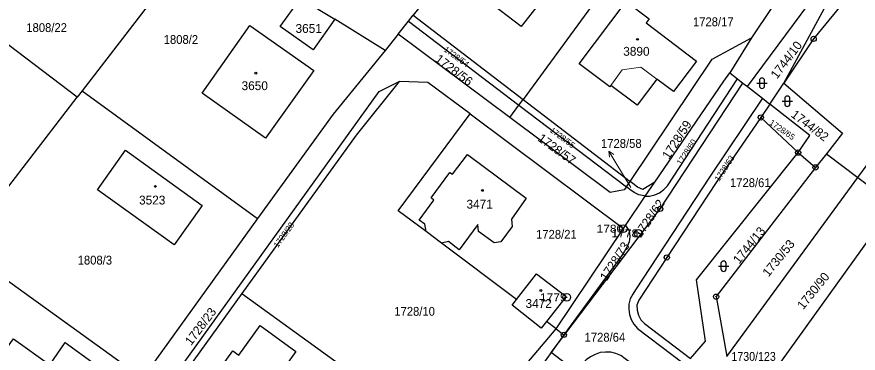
# Model space of a CAD drawing. Extents: x -679733 to -673243, y -1075091 to -1066557.
# Drawn here: x -677143.9 to -676982.3, y -1072239.2 to -1072174.7 of the extents above; entities that cross this region are included whole.
import ezdxf
from ezdxf.enums import TextEntityAlignment as Align

# ---------------------------------------------------------------- set-up
doc = ezdxf.new("R2010")
doc.units = 0
doc.header["$LTSCALE"] = 0.68
for name, color, linetype, lineweight in [('1', 7, 'Continuous', 25), ('3', 7, 'Continuous', 25), ('4', 7, 'Continuous', 13), ('5', 7, 'Continuous', 25), ('7', 7, 'Continuous', 13), ('8', 7, 'Continuous', 25)]:
    doc.layers.add(name, color=color, linetype=linetype, lineweight=lineweight)
doc.layers.add('2', color=7, linetype='Continuous')

msp = doc.modelspace()

# ---------------------------------------------------------------- linework, layer by layer
at = {"layer": '1'}
for p, q in [((-677021.42, -1072156.06), (-677046.63, -1072190.51)), ((-677089.42, -1072171.09), (-677082.85, -1072175.14)), ((-677073.16, -1072181.12), (-677082.85, -1072175.14)), ((-677068.7, -1072175.5), (-677047.45, -1072191.63)), ((-677002.77, -1072178.71), (-677006.93, -1072185.42)), ((-676999.25, -1072191.43), (-676996.56, -1072187.43)), ((-677131.37, -1072188.86), (-677132.33, -1072190.1)), ((-677049.19, -1072194.01), (-677047.45, -1072191.63)), ((-677047.45, -1072191.63), (-677046.63, -1072190.51)), ((-677047.45, -1072191.63), (-677026.81, -1072207.31)), ((-677046.63, -1072190.51), (-677026.1, -1072206.25)), ((-676993.8, -1072200.73), (-676990.45, -1072203.57)), ((-676988.38, -1072200.94), (-676982.32, -1072205.52)), ((-677026.81, -1072207.31), (-677026.1, -1072206.25)), ((-677007.53, -1072239.86), (-676982.32, -1072205.52)), ((-676982.32, -1072205.52), (-676975.41, -1072210.74)), ((-677023.17, -1072209.06), (-677021.37, -1072206.38)), ((-677002.87, -1072248.9), (-676975.41, -1072210.74)), ((-677040.31, -1072234.56), (-677027.35, -1072215.28)), ((-677154.6, -1072218.99), (-677119.75, -1072243.96)), ((-677040.31, -1072234.56), (-677038.82, -1072235.71)), ((-677038.82, -1072235.71), (-677041.29, -1072239.09))]:
    msp.add_line(p, q, dxfattribs=at)
for points in [[(-677003.56, -1072188.05), (-676937.07, -1072098.47), (-676924.77, -1072082.25), (-676901.08, -1072050.53), (-676900.33, -1072051.15)], [(-676926.11, -1072076.11), (-676932.42, -1072084.22), (-676965.77, -1072128.57), (-676982.28, -1072150.91), (-676998.86, -1072172.9), (-677002.77, -1072178.71)], [(-676996.56, -1072187.43), (-676985.94, -1072167.77), (-676927.29, -1072088.05)], [(-676924.4, -1072090.21), (-676960.77, -1072142.26), (-676990.83, -1072178.91), (-676996.56, -1072187.43)], [(-677082.85, -1072175.14), (-677086.97, -1072181.02), (-677093.32, -1072176.54), (-677089.42, -1072171.09), (-677108.59, -1072159.26), (-677131.37, -1072188.86), (-677097.67, -1072213.39)], [(-677056.82, -1072160.52), (-677062.04, -1072167.1), (-677067.77, -1072174.34), (-677046.63, -1072190.51)], [(-677154.6, -1072218.99), (-677132.33, -1072190.1), (-677153.76, -1072173.89), (-677171.45, -1072197.13), (-677175.99, -1072203.1)], [(-677070.68, -1072177.99), (-677068.7, -1072175.5), (-677067.77, -1072174.34)], [(-677026.81, -1072207.31), (-677027.21, -1072207.9), (-677029.93, -1072208.37), (-677049.19, -1072194.01), (-677070.68, -1072177.99), (-677073.16, -1072181.12)], [(-677026.1, -1072206.25), (-677010.31, -1072182.77), (-677002.77, -1072178.71)], [(-677073.16, -1072181.12), (-677083.15, -1072193.33), (-677097.67, -1072213.39), (-677119.75, -1072243.96), (-677138.7, -1072270.17), (-677157.58, -1072296.32)], [(-676982.32, -1072205.52), (-676964.73, -1072181.57), (-676957.44, -1072186.84), (-676936.58, -1072201.92), (-676934.58, -1072203.37)], [(-677023.17, -1072209.06), (-677022.36, -1072209.08), (-677021.37, -1072208.84), (-677020.43, -1072208.43), (-677019.61, -1072207.8), (-677018.91, -1072207.08), (-677005.45, -1072186.58)], [(-677021.37, -1072206.38), (-677008.05, -1072187.02), (-677006.93, -1072185.42)], [(-677006.93, -1072185.42), (-677005.45, -1072186.58), (-677004.4, -1072187.4), (-677003.56, -1072188.05)], [(-677137.29, -1072278.46), (-677138.25, -1072277.77), (-677074.28, -1072189.03), (-677070.45, -1072187.06)], [(-677070.45, -1072187.06), (-677078.7, -1072197.36), (-677100.67, -1072227.78), (-677081.22, -1072241.84), (-677059.66, -1072257.41), (-677040.31, -1072234.56), (-677042.16, -1072233.17)], [(-677056.81, -1072193.31), (-677064.93, -1072187.26), (-677070.45, -1072187.06)], [(-677041.29, -1072239.09), (-677020.3, -1072211.54), (-677004.4, -1072187.4)], [(-677003.56, -1072188.05), (-677000.68, -1072190.31), (-676999.25, -1072191.43)], [(-676996.56, -1072187.43), (-676985.27, -1072196.98), (-676988.38, -1072200.94), (-676990.45, -1072203.57)], [(-677000.68, -1072190.31), (-677010.81, -1072205.46), (-677025.05, -1072227.04), (-677025.58, -1072227.92), (-677026.06, -1072228.81), (-677026.31, -1072229.79), (-677026.34, -1072230.8), (-677026.21, -1072231.82), (-677025.88, -1072232.78), (-677025.36, -1072233.67), (-677024.7, -1072234.47), (-677011.5, -1072244.49)], [(-676999.25, -1072191.43), (-677000.98, -1072193.99), (-676993.8, -1072200.73)], [(-676993.8, -1072200.73), (-676991.56, -1072197.46), (-676999.25, -1072191.43)], [(-677065.31, -1072215.87), (-677070.68, -1072211.91), (-677056.81, -1072193.31)], [(-677056.81, -1072193.31), (-677027.35, -1072215.28), (-677026.98, -1072214.73), (-677023.17, -1072209.06)], [(-677000.98, -1072193.99), (-677009.55, -1072206.46), (-677019.04, -1072220.85), (-677024.42, -1072229.04), (-677024.78, -1072230), (-677024.76, -1072230.97), (-677024.5, -1072231.92), (-677024.01, -1072232.8), (-677023.32, -1072233.51), (-677014.49, -1072240.22)], [(-677065.31, -1072215.87), (-677065.55, -1072214.46), (-677066.63, -1072213.67), (-677063.79, -1072209.83), (-677064.31, -1072209.44), (-677060.7, -1072204.55), (-677060.19, -1072204.89), (-677057.34, -1072201.07), (-677046.04, -1072209.49), (-677048.9, -1072213.51), (-677048.73, -1072214.89), (-677050.93, -1072217.85), (-677052.19, -1072218.04), (-677055.23, -1072215.86), (-677055.36, -1072214.56), (-677058.94, -1072219.38), (-677060.97, -1072217.79), (-677062.31, -1072218.1)], [(-677014.49, -1072240.22), (-677011.6, -1072236.95), (-677013.33, -1072225.14), (-676993.8, -1072200.73)], [(-676990.45, -1072203.57), (-677009.57, -1072228.38), (-677007.53, -1072239.86)], [(-677021.37, -1072206.38), (-677023.64, -1072207.84), (-677024.69, -1072207.39), (-677025.59, -1072206.64), (-677026.1, -1072206.25)], [(-677023.17, -1072209.06), (-677023.38, -1072209.05), (-677024.39, -1072208.85), (-677025.29, -1072208.4), (-677026.13, -1072207.83), (-677026.81, -1072207.31)], [(-677042.16, -1072233.17), (-677043.16, -1072234.45), (-677048.78, -1072230.02), (-677047.9, -1072228.9), (-677062.31, -1072218.1), (-677065.31, -1072215.87)], [(-677026.98, -1072214.73), (-677026.28, -1072215.76), (-677026.13, -1072216.83), (-677026.28, -1072217.83), (-677026.67, -1072218.76), (-677027.15, -1072219.65), (-677027.69, -1072220.49), (-677038.82, -1072235.71)], [(-677047.9, -1072228.9), (-677044.06, -1072224.02), (-677038.38, -1072228.38), (-677042.16, -1072233.17)], [(-677100.67, -1072227.78), (-677124.1, -1072260.21), (-677104.64, -1072274.26)], [(-677104.87, -1072255.34), (-677104.07, -1072254.32), (-677109.18, -1072250.61), (-677106.84, -1072247.36), (-677107.98, -1072246.53), (-677102.4, -1072238.8), (-677101.25, -1072239.61), (-677097.17, -1072233.94), (-677090.3, -1072238.92), (-677094.4, -1072244.63), (-677088.97, -1072248.54), (-677094.54, -1072256.24), (-677097.69, -1072261.24)], [(-677019.54, -1072245.93), (-677027.03, -1072240.29), (-677027.88, -1072239.66), (-677028.81, -1072239.26), (-677029.8, -1072239.05), (-677030.81, -1072239.03), (-677031.83, -1072239.12), (-677032.79, -1072239.47), (-677033.69, -1072239.9), (-677034.52, -1072240.49), (-677035.28, -1072241.18), (-677036.59, -1072242.68), (-677041.29, -1072239.09), (-677056.26, -1072259.8), (-677079.53, -1072292.18)]]:
    msp.add_lwpolyline(points, dxfattribs=at)
for points in [[(-677047.03, -1072176.53), (-677053.73, -1072171.35), (-677051.28, -1072168.19), (-677055.37, -1072165.02), (-677050.84, -1072159.13), (-677039.96, -1072167.5)], [(-677022.43, -1072175.06), (-677023.03, -1072175.85), (-677013.34, -1072183.15), (-677017.74, -1072189.03), (-677020.94, -1072186.65), (-677024.75, -1072191.65), (-677029.79, -1072187.85), (-677030, -1072188.09), (-677035.87, -1072183.69), (-677026.86, -1072171.73)], [(-677086.89, -1072184.95), (-677096.16, -1072197.96), (-677108.34, -1072189.32), (-677099.14, -1072176.35)], [(-677108.3, -1072210.87), (-677113.7, -1072218.46), (-677128.44, -1072207.86), (-677123.08, -1072200.29)], [(-677128.79, -1072241.43), (-677134.68, -1072249.56), (-677135.9, -1072248.66), (-677137.8, -1072251.25), (-677149.34, -1072242.93), (-677144.6, -1072236.47), (-677137.62, -1072241.49), (-677134.63, -1072237.21)]]:
    msp.add_lwpolyline(points, close=True, dxfattribs=at)
at = {"layer": '3'}
for p, q in [((-677001.251, -1072186.911), (-677001.251, -1072187.912)), ((-677000.249, -1072187.912), (-677000.249, -1072186.911)), ((-677001.751, -1072187.411), (-676999.749, -1072187.411)), ((-676996.891, -1072190.871), (-676994.889, -1072190.871)), ((-676996.391, -1072190.371), (-676996.391, -1072191.372)), ((-676995.389, -1072191.372), (-676995.389, -1072190.371)), ((-677008.631, -1072222.041), (-677008.631, -1072223.042)), ((-677007.629, -1072223.042), (-677007.629, -1072222.041)), ((-677009.131, -1072222.541), (-677007.129, -1072222.541))]:
    msp.add_line(p, q, dxfattribs=at)
for centre, start, end in [((-677000.75, -1072186.9109), 0, 180), ((-677000.75, -1072187.9109), 180, 359.98789), ((-676995.89, -1072190.3709), 0, 180), ((-676995.89, -1072191.3709), 180, 359.98789), ((-677008.13, -1072222.0409), 0, 180), ((-677008.13, -1072223.0409), 180, 359.98789)]:
    msp.add_arc(centre, 0.5, start, end, dxfattribs=at)
at = {"layer": '4'}
for p, q in [((-677029.79, -1072187.85), (-677027.6, -1072184.87)), ((-677027.6, -1072184.87), (-677024.01, -1072184.36)), ((-677024.01, -1072184.36), (-677020.94, -1072186.65))]:
    msp.add_line(p, q, dxfattribs=at)
at = {"layer": '5'}
for centre in [(-677024.6568, -1072178.9892), (-677098.0168, -1072185.4692), (-677117.3168, -1072207.2192), (-677054.4768, -1072207.9792), (-677043.2368, -1072227.1892)]:
    msp.add_circle(centre, 0.175, dxfattribs=at)
at = {"layer": '7'}
msp.add_line((-677030.166, -1072200.468), (-677030.079, -1072201.584), dxfattribs=at)
msp.add_lwpolyline([(-677025.94, -1072207.45), (-677028.62, -1072203.04), (-677030.166, -1072200.468), (-677029.221, -1072201.068)], dxfattribs=at)
at = {"layer": '8'}
for centre, radius in [((-676990.83, -1072178.9099), 0.5), ((-676990.83, -1072178.9099), 0.0303), ((-677000.98, -1072193.9899), 0.5), ((-677000.98, -1072193.9899), 0.0303), ((-676993.8, -1072200.7299), 0.5), ((-676993.8, -1072200.7299), 0.0303), ((-676990.45, -1072203.5699), 0.5), ((-676990.45, -1072203.5699), 0.0303), ((-677020.3, -1072211.5399), 0.5), ((-677020.3, -1072211.5399), 0.0303), ((-677027.41, -1072215.3298), 0.75), ((-677027.41, -1072215.3298), 0.03), ((-677024.54, -1072216.2298), 0.75), ((-677024.54, -1072216.2298), 0.03), ((-677019.04, -1072220.8499), 0.5), ((-677019.04, -1072220.8499), 0.0303), ((-677038.29, -1072228.4998), 0.75), ((-677038.29, -1072228.4998), 0.03), ((-677009.57, -1072228.3799), 0.5), ((-677009.57, -1072228.3799), 0.0303), ((-677038.8199, -1072235.7099), 0.5), ((-677038.8199, -1072235.7099), 0.0303)]:
    msp.add_circle(centre, radius, dxfattribs=at)

# ---------------------------------------------------------------- texts
at = {"layer": '2'}
for s, width, p in [('1728/17', 0.95, (-677014.01, -1072176.47)), ('1808/22', 0.95, (-677142.11, -1072177.59)), ('1808/2', 0.95, (-677115.71, -1072179.87)), ('1728/61', 0.95, (-677006.9, -1072207.35)), ('1728/21', 0.95, (-677044.16, -1072217.269)), ('1808/3', 0.95, (-677132.24, -1072222.22)), ('1728/10', 0.95, (-677071.4, -1072232.05)), ('1728/64', 0.95, (-677034.84, -1072237.019)), ('1730/123', 0.9, (-677006.63, -1072240.7))]:
    msp.add_text(s, height=1.7, dxfattribs=dict(at, width=width)).set_placement(p)
for s, p in [('3651', (-677090.38, -1072177.749)), ('3890', (-677027.41, -1072182.14)), ('3650', (-677100.75, -1072188.739)), ('3523', (-677120.45, -1072210.69)), ('3471', (-677057.53, -1072211.47)), ('3472', (-677046.19, -1072230.54))]:
    msp.add_text(s, height=1.7, dxfattribs=at).set_placement(p)
for s, height, rotation, p in [('1744/10', 1.7, 53, (-676997.871, -1072186.721)), ('1728/54', 1.14, 324, (-677062.015, -1072181.181)), ('1728/56', 1.7, 323, (-677063.701, -1072183.088)), ('1728/59', 1.7, 57, (-677018.637, -1072202.162)), ('1728/65', 1.14, 325, (-676999.446, -1072195.236)), ('1728/55', 1.14, 323, (-677041.623, -1072196.655)), ('1728/57', 1.7, 324, (-677043.989, -1072198.337)), ('1728/60', 1.14, 57, (-677016.261, -1072203.25)), ('1728/63', 1.14, 57, (-677008.981, -1072206.37)), ('1728/62', 1.7, 55, (-677024.073, -1072217.217)), ('1728/28', 1.14, 54, (-677093.778, -1072219.085)), ('1744/13', 1.7, 51, (-677005.139, -1072222.234)), ('1730/53', 1.7, 51, (-676999.499, -1072224.704)), ('1730/90', 1.7, 51, (-676992.829, -1072230.984)), ('1728/23', 1.7, 53, (-677110.431, -1072237.871))]:
    msp.add_text(s, height=height, rotation=rotation, dxfattribs=at).set_placement(p)
for s, rotation, p in [('1744/82', 323, (-676992.0395, -1072196.206)), ('1728/73', 57, (-677028.3462, -1072222.0434))]:
    msp.add_text(s, height=1.7, rotation=rotation, dxfattribs=at).set_placement(p, align=Align.CENTER)
at = {"layer": '2', "width": 0.95}
msp.add_text('1728/58', height=1.7, dxfattribs=at).set_placement((-677023.88, -1072199.82), align=Align.RIGHT)
at = {"layer": '8', "width": 1.15}
for s, p in [('1780', (-677027.409, -1072216.08)), ('1778', (-677024.539, -1072216.98)), ('1779', (-677038.289, -1072229.25))]:
    msp.add_text(s, height=1.5, dxfattribs=at).set_placement(p, align=Align.RIGHT)

doc.saveas('drawing.dxf')
